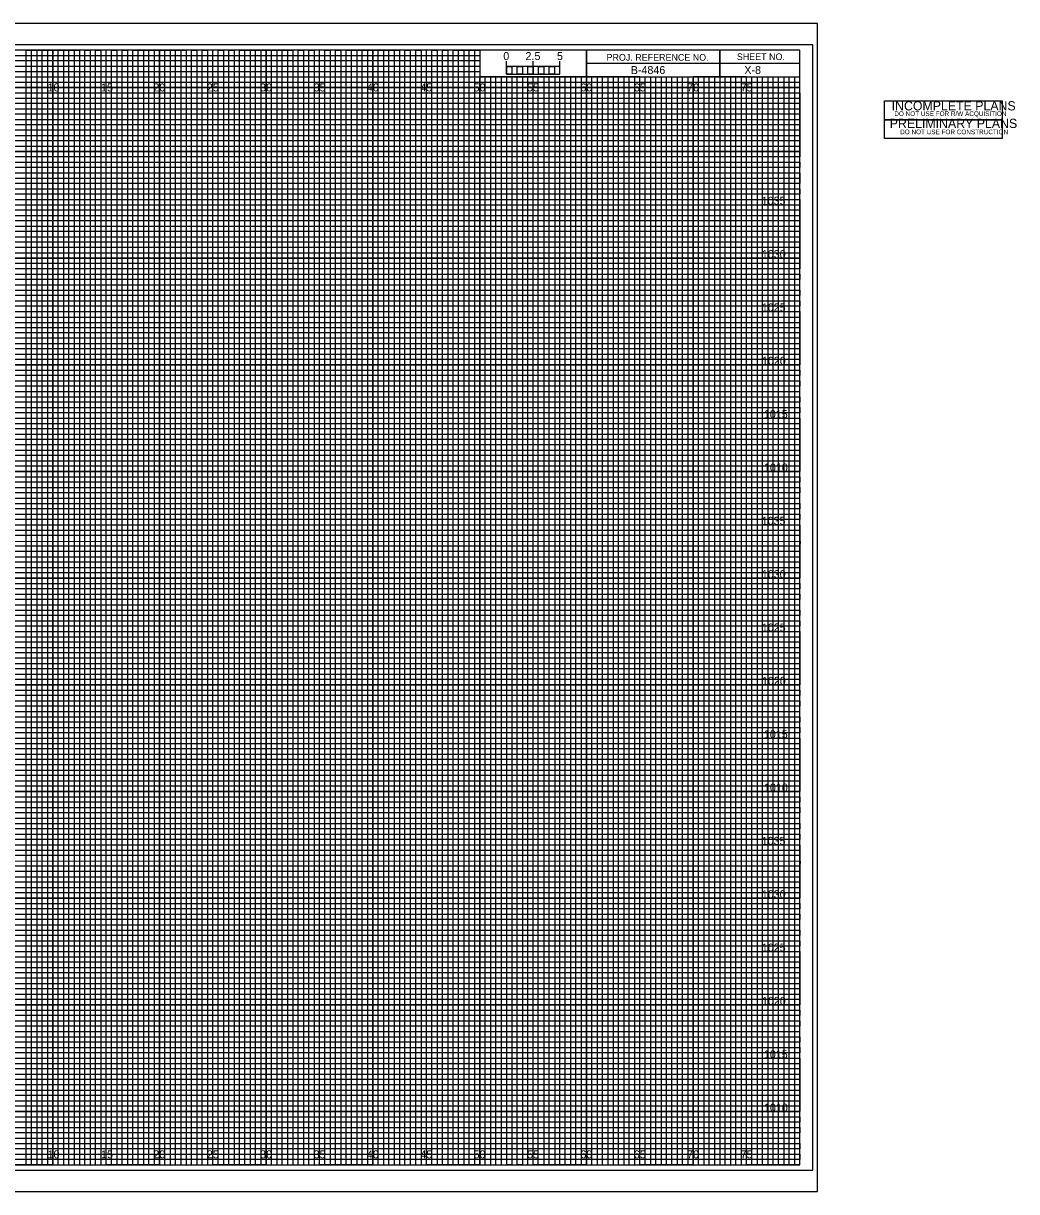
# Model space of a CAD drawing. Extents: x -7 to 180, y -2 to 107.
# Drawn here: x 87.2 to 180.3, y -2.5 to 107 of the extents above; entities that cross this region are included whole.
import ezdxf

# ---------------------------------------------------------------- set-up
doc = ezdxf.new("R2010")
doc.units = 0
for name, color, linetype in [('Default', 7, 'Continuous'), ('Exist Cross Section Cell', 7, 'Continuous'), ('Exist XS Center Line Elevation Label', 7, 'Continuous'), ('Exist XS Ground Line', 7, 'Continuous'), ('Prop CMT Concrete Structures', 7, 'Continuous'), ('Prop CMT Guardrail Graphics', 7, 'Continuous'), ('Prop CMT Guardrail Widen Shoulder', 7, 'Continuous'), ('Prop CMT Pvmt Course 1', 7, 'Continuous'), ('Prop CMT Pvmt Surface', 7, 'Continuous'), ('Prop CMT Pvmt Surface Shoulder', 7, 'Continuous'), ('Prop CMT Shld Paved Course 1', 7, 'Continuous'), ('Prop CMT Shoulder Point', 7, 'Continuous'), ('Prop CMT Slope Grass', 7, 'Continuous'), ('Prop CMT Subgrade Earthwork', 7, 'Continuous'), ('Prop XS SE Text', 7, 'Continuous'), ('Typical Text Label CELL', 7, 'Continuous')]:
    doc.layers.add(name, color=color, linetype=linetype)

msp = doc.modelspace()

# ---------------------------------------------------------------- linework, layer by layer
at = {"layer": 'Default'}
for points in [[(167.92, 97.97), (167.92, 99.73), (178.95, 99.73), (178.95, 97.97)], [(167.92, 96.2), (167.92, 97.97), (178.95, 97.97), (178.95, 96.2)]]:
    msp.add_lwpolyline(points, close=True, dxfattribs=at)
at = {"layer": 'Exist XS Center Line Elevation Label'}
for points in [[(82.5, 0), (87.5, 0), (87.5, 104.5), (92.5, 104.5), (92.5, 0), (97.5, 0), (97.5, 104.5), (102.5, 104.5), (102.5, 0), (107.5, 0), (107.5, 104.5), (112.5, 104.5), (112.5, 0), (117.5, 0), (117.5, 104.5), (122.5, 104.5), (122.5, 0), (127.5, 0), (127.5, 104.5), (129.97, 104.5), (130, 104.5), (130, 102), (132.5, 102), (132.5, 0), (137.5, 0), (137.5, 102), (142.5, 102), (142.5, 0), (147.5, 0), (147.5, 102), (152.5, 102), (152.5, 0), (157.5, 0), (157.5, 102)], [(0, 102), (137.5, 102)], [(0, 92.5), (160, 92.5), (160, 97.5), (0, 97.5)], [(0, 82.5), (160, 82.5), (160, 87.5), (0, 87.5)], [(0, 72.5), (160, 72.5), (160, 77.5), (0, 77.5)], [(0, 62.5), (160, 62.5), (160, 67.5), (0, 67.5)], [(0, 52.5), (160, 52.5), (160, 57.5), (0, 57.5)], [(0, 42.5), (160, 42.5), (160, 47.5), (0, 47.5)], [(0, 32.5), (160, 32.5), (160, 37.5), (0, 37.5)], [(0, 22.5), (160, 22.5), (160, 27.5), (0, 27.5)], [(0, 12.5), (160, 12.5), (160, 17.5), (0, 17.5)], [(0, 2.5), (160, 2.5), (160, 7.5), (0, 7.5)]]:
    msp.add_lwpolyline(points, dxfattribs=at)
at = {"layer": 'Exist XS Ground Line'}
for p, q in [((95, 104.5), (90, 104.5)), ((90, 104.5), (90, 0)), ((95, 0), (95, 104.5)), ((105, 104.5), (100, 104.5)), ((100, 104.5), (100, 0)), ((105, 0), (105, 104.5)), ((115, 104.5), (110, 104.5)), ((110, 104.5), (110, 0)), ((115, 0), (115, 104.5)), ((125, 104.5), (120, 104.5)), ((120, 104.5), (120, 0)), ((125, 0), (125, 104.5)), ((130, 104.5), (130, 0)), ((135, 0), (135, 102)), ((145, 102), (140, 102)), ((140, 102), (140, 0)), ((145, 0), (145, 102)), ((155, 102), (150, 102)), ((150, 102), (150, 0)), ((155, 0), (155, 102)), ((90, 0), (85, 0)), ((100, 0), (95, 0)), ((110, 0), (105, 0)), ((120, 0), (115, 0)), ((130, 0), (125, 0)), ((140, 0), (135, 0)), ((150, 0), (145, 0)), ((160, 0), (155, 0)), ((160, 0), (160, 0))]:
    msp.add_line(p, q, dxfattribs=at)
for points in [[(0, 100), (160, 100), (160, 95), (0, 95)], [(0, 90), (160, 90), (160, 85), (0, 85)], [(0, 80), (160, 80), (160, 75), (0, 75)], [(0, 70), (160, 70), (160, 65), (0, 65)], [(0, 60), (160, 60), (160, 55), (0, 55)], [(0, 50), (160, 50), (160, 45), (0, 45)], [(0, 40), (160, 40), (160, 35), (0, 35)], [(0, 30), (160, 30), (160, 25), (0, 25)], [(0, 20), (160, 20), (160, 15), (0, 15)], [(0, 10), (160, 10), (160, 5), (0, 5)]]:
    msp.add_lwpolyline(points, dxfattribs=at)
at = {"layer": 'Prop CMT Concrete Structures'}
for p, q in [((90, 0), (90, 104.5)), ((95, 0), (95, 104.5)), ((100, 0), (100, 104.5)), ((105, 0), (105, 104.5)), ((110, 0), (110, 104.5)), ((115, 0), (115, 104.5)), ((120, 0), (120, 104.5)), ((125, 0), (125, 104.5)), ((130, 0), (130, 101.84)), ((135, 0), (135, 101.84)), ((140, 0), (140, 101.84)), ((145, 0), (145, 101.84)), ((150, 0), (150, 101.84)), ((155, 0), (155, 101.84)), ((0, 100), (160, 100)), ((0, 95), (160, 95)), ((0, 90), (160, 90)), ((0, 85), (160, 85)), ((0, 80), (160, 80)), ((0, 75), (160, 75)), ((0, 70), (160, 70)), ((0, 65), (160, 65)), ((0, 60), (160, 60)), ((0, 55), (160, 55)), ((0, 50), (160, 50)), ((0, 45), (160, 45)), ((0, 40), (160, 40)), ((0, 35), (160, 35)), ((0, 30), (160, 30)), ((0, 25), (160, 25)), ((0, 20), (160, 20)), ((0, 15), (160, 15)), ((0, 10), (160, 10)), ((0, 5), (160, 5))]:
    msp.add_line(p, q, dxfattribs=at)
at = {"layer": 'Prop CMT Guardrail Widen Shoulder'}
for p, q in [((161.65, 107), (-6.7, 107)), ((-6.7, -2.5), (161.65, -2.5))]:
    msp.add_line(p, q, dxfattribs=at)
at = {"layer": 'Prop CMT Pvmt Course 1'}
msp.add_lwpolyline([(-6.7, -2.5), (161.65, -2.5), (161.65, 107), (-6.7, 107)], close=True, dxfattribs=at)
at = {"layer": 'Prop CMT Pvmt Surface'}
for p, q in [((133.5, 102), (133, 102)), ((133, 102), (133, 0)), ((133.5, 0), (133.5, 102)), ((134.5, 102), (134, 102)), ((134, 102), (134, 0)), ((134.5, 0), (134.5, 102)), ((133, 0), (132.5, 0)), ((134, 0), (133.5, 0))]:
    msp.add_line(p, q, dxfattribs=at)
for points in [[(87.5, 0), (88, 0), (88, 104.5), (88.5, 104.5), (88.5, 0)], [(88.5, 0), (89, 0), (89, 104.5), (89.5, 104.5), (89.5, 0)], [(90, 0), (90.5, 0), (90.5, 104.5), (91, 104.5), (91, 0)], [(91, 0), (91.5, 0), (91.5, 104.5), (92, 104.5), (92, 0)], [(92.5, 0), (93, 0), (93, 104.5), (93.5, 104.5), (93.5, 0)], [(93.5, 0), (94, 0), (94, 104.5), (94.5, 104.5), (94.5, 0)], [(95, 0), (95.5, 0), (95.5, 104.5), (96, 104.5), (96, 0)], [(96, 0), (96.5, 0), (96.5, 104.5), (97, 104.5), (97, 0)], [(97.5, 0), (98, 0), (98, 104.5), (98.5, 104.5), (98.5, 0)], [(98.5, 0), (99, 0), (99, 104.5), (99.5, 104.5), (99.5, 0)], [(100, 0), (100.5, 0), (100.5, 104.5), (101, 104.5), (101, 0)], [(101, 0), (101.5, 0), (101.5, 104.5), (102, 104.5), (102, 0)], [(102.5, 0), (103, 0), (103, 104.5), (103.5, 104.5), (103.5, 0)], [(103.5, 0), (104, 0), (104, 104.5), (104.5, 104.5), (104.5, 0)], [(105, 0), (105.5, 0), (105.5, 104.5), (106, 104.5), (106, 0)], [(106, 0), (106.5, 0), (106.5, 104.5), (107, 104.5), (107, 0)], [(107.5, 0), (108, 0), (108, 104.5), (108.5, 104.5), (108.5, 0)], [(108.5, 0), (109, 0), (109, 104.5), (109.5, 104.5), (109.5, 0)], [(110, 0), (110.5, 0), (110.5, 104.5), (111, 104.5), (111, 0)], [(111, 0), (111.5, 0), (111.5, 104.5), (112, 104.5), (112, 0)], [(112.5, 0), (113, 0), (113, 104.5), (113.5, 104.5), (113.5, 0)], [(113.5, 0), (114, 0), (114, 104.5), (114.5, 104.5), (114.5, 0)], [(115, 0), (115.5, 0), (115.5, 104.5), (116, 104.5), (116, 0)], [(116, 0), (116.5, 0), (116.5, 104.5), (117, 104.5), (117, 0)], [(117.5, 0), (118, 0), (118, 104.5), (118.5, 104.5), (118.5, 0)], [(118.5, 0), (119, 0), (119, 104.5), (119.5, 104.5), (119.5, 0)], [(120, 0), (120.5, 0), (120.5, 104.5), (121, 104.5), (121, 0)], [(121, 0), (121.5, 0), (121.5, 104.5), (122, 104.5), (122, 0)], [(122.5, 0), (123, 0), (123, 104.5), (123.5, 104.5), (123.5, 0)], [(123.5, 0), (124, 0), (124, 104.5), (124.5, 104.5), (124.5, 0)], [(125, 0), (125.5, 0), (125.5, 104.5), (126, 104.5), (126, 0)], [(126, 0), (126.5, 0), (126.5, 104.5), (127, 104.5), (127, 0)], [(127.5, 0), (128, 0), (128, 104.5), (128.5, 104.5), (128.5, 0)], [(128.5, 0), (129, 0), (129, 104.5), (129.5, 104.5), (129.5, 0)], [(130, 0), (130.5, 0), (130.5, 102), (131.01, 102), (131.01, 0)], [(131, 0), (131.5, 0), (131.5, 102), (132, 102), (132, 0)], [(135, 0), (135.49, 0), (135.49, 102), (136, 102), (136, 0)], [(136, 0), (136.5, 0), (136.5, 102), (137.03, 102), (137.03, 0)], [(137.5, 0), (138, 0), (138, 102), (138.5, 102), (138.5, 0)], [(138.5, 0), (139, 0), (139, 102), (139.5, 102), (139.5, 0)], [(140, 0), (140.5, 0), (140.5, 102), (141, 102), (141, 0)], [(141, 0), (141.5, 0), (141.5, 102), (142, 102), (142, 0)], [(142.5, 0), (143, 0), (143, 102), (143.5, 102), (143.5, 0)], [(143.5, 0), (144, 0), (144, 102), (144.5, 102), (144.5, 0)], [(145, 0), (145.5, 0), (145.5, 102), (146, 102), (146, 0)], [(146, 0), (146.5, 0), (146.5, 102), (147, 102), (147, 0)], [(147.5, 0), (148, 0), (148, 102), (148.5, 102), (148.5, 0)], [(148.5, 0), (149, 0), (149, 102), (149.5, 102), (149.5, 0)], [(150, 0), (150.5, 0), (150.5, 102), (151, 102), (151, 0)], [(151, 0), (151.5, 0), (151.5, 102), (152, 102), (152, 0)], [(152.5, 0), (153, 0), (153, 102), (153.5, 102), (153.5, 0)], [(153.5, 0), (154, 0), (154, 102), (154.5, 102), (154.5, 0)], [(155, 0), (155.5, 0), (155.5, 102), (156, 102), (156, 0)], [(156, 0), (156.5, 0), (156.5, 102), (157, 102), (157, 0)], [(157.5, 0), (158, 0), (158, 102), (158.5, 102), (158.5, 0)], [(158.5, 0), (159, 0), (159, 102), (159.5, 102), (159.5, 0)]]:
    msp.add_lwpolyline(points, dxfattribs=at)
at = {"layer": 'Prop CMT Pvmt Surface Shoulder'}
for p, q in [((132.5, 102.25), (132.5, 103.45)), ((132.5, 102.95), (132.5, 103.45)), ((135, 102.25), (135, 103.45)), ((137.5, 102.25), (137.5, 103.45)), ((137.5, 102.95), (137.5, 103.45))]:
    msp.add_line(p, q, dxfattribs=at)
for points in [[(137.5, 102.95), (132.5, 102.95), (132.5, 102.25), (137.5, 102.25)], [(132.5, 102.95), (133, 102.95), (133, 102.25), (132.5, 102.25)], [(133.5, 102.95), (134, 102.95), (134, 102.25), (133.5, 102.25)], [(134.5, 102.95), (135, 102.95), (135, 102.25), (134.5, 102.25)], [(135.5, 102.95), (136, 102.95), (136, 102.25), (135.5, 102.25)], [(136.5, 102.95), (137, 102.95), (137, 102.25), (136.5, 102.25)]]:
    msp.add_lwpolyline(points, close=True, dxfattribs=at)
at = {"layer": 'Prop CMT Shld Paved Course 1'}
for p, q in [((0, 104), (130, 104)), ((130, 103.49), (0, 103.49)), ((0, 103), (130, 103)), ((130, 104), (130, 103.49)), ((130, 103), (130, 102.45)), ((130, 102.45), (0, 102.45)), ((0, 101.5), (160, 101.5))]:
    msp.add_line(p, q, dxfattribs=at)
for points in [[(0, 101), (135, 101), (160, 101), (160, 101), (0, 101)], [(0, 100.5), (160, 100.5), (160, 99.5), (0, 99.5)], [(0, 99), (160, 99), (160, 98.5), (0, 98.49)], [(0, 98), (160, 98), (160, 97), (0, 97)], [(0, 96.5), (160, 96.5), (160, 96), (0, 96)], [(0, 95.5), (160, 95.5), (160, 94.5), (0, 94.5)], [(0, 94), (160, 94), (160, 93.5), (0, 93.5)], [(0, 93), (160, 93), (160, 92), (0, 92)], [(0, 91.5), (160, 91.5), (160, 91), (0, 91)], [(0, 90.5), (160, 90.5), (160, 89.5), (0, 89.5)], [(0, 89), (160, 89), (160, 88.5), (0, 88.5)], [(0, 88), (160, 88), (160, 86.98), (160, 86.5), (160, 86), (0, 86)], [(0, 87), (160, 87), (160, 86.5), (0, 86.5)], [(0, 85.5), (160, 85.5), (160, 84.5), (0, 84.52)], [(0, 84.52), (160, 84.5), (160, 84), (0, 84)], [(0, 83.5), (160, 83.5), (160, 83), (0, 83)], [(0, 82), (160, 82), (160, 81.5), (0, 81.5)], [(0, 81), (160, 81), (160, 80.5), (0, 80.5)], [(-0.04, 79.45), (160, 79.45), (160, 78.94), (-0.04, 78.94)], [(0, 78.5), (160, 78.5), (160, 78), (0, 78)], [(0, 77), (160, 77), (160, 76.5), (0, 76.5)], [(0, 76), (160, 76), (160, 75.5), (0, 75.5)], [(0, 74.5), (160, 74.5), (160, 74), (0, 74)], [(0, 73.5), (160, 73.5), (160, 73), (0, 73)], [(0, 72), (160, 72), (160, 71.5), (0, 71.5)], [(0, 71), (160, 71), (160, 70.5), (0, 70.5)], [(0, 69.5), (160, 69.5), (160, 68.99), (0, 69)], [(0, 68.5), (160, 68.5), (160, 68), (0, 68)], [(0, 67), (160, 67), (160, 66.5), (0, 66.5)], [(0, 66), (160, 66), (160, 65.5), (0, 65.5)], [(0, 64.5), (160, 64.5), (160, 64), (0, 64)], [(0, 63.5), (160, 63.5), (160, 63), (0, 63)], [(0, 62), (160, 62), (160, 61.5), (0, 61.5)], [(0, 61), (160, 61), (160, 60.5), (0, 60.5)], [(0, 59.5), (160, 59.5), (160, 59), (0, 59)], [(0, 58.5), (160.03, 58.45), (160, 58), (0, 58)], [(0, 57), (160, 57), (160, 56.5), (0, 56.5)], [(0, 56), (160, 56), (160, 55.5), (0, 55.5)], [(0, 54.5), (160, 54.5), (160, 54), (0, 54)], [(0, 53.5), (160, 53.5), (160, 53), (0, 53)], [(0, 52), (160, 52), (160, 51.5), (0, 51.5)], [(0, 51), (160, 51), (160, 50.5), (0, 50.5)], [(0, 49.5), (160, 49.5), (160, 49), (0, 49)], [(0, 48.5), (160, 48.5), (160, 48), (0, 48)], [(0, 47), (160, 47), (160, 46.5), (0, 46.5)], [(0, 46), (160, 46), (160, 45.5), (0, 45.5)], [(0, 44.5), (160, 44.5), (160, 44), (0, 44)], [(0, 43.5), (160, 43.5), (160, 43), (0, 43)], [(0, 42), (160, 42), (160, 41.5), (0, 41.5)], [(0, 41), (160, 41), (160, 40.5), (0, 40.5)], [(0, 39.5), (160, 39.5), (160, 38.99), (0, 39)], [(0, 38.5), (160, 38.5), (160, 38), (0, 38)], [(0, 37), (160, 37), (160, 36.5), (0, 36.5)], [(0, 36), (160, 36), (160, 35.5), (0, 35.5)], [(0, 34.5), (160, 34.5), (160, 34), (0, 34)], [(0, 33.5), (160, 33.5), (160, 33), (0, 33)], [(0, 32), (160, 32), (160, 31.5), (0, 31.5)], [(0, 31), (160, 31), (160, 30.5), (0, 30.5)], [(0, 29.5), (160, 29.5), (160, 29), (0, 29)], [(0, 28.5), (160.03, 28.46), (160, 28), (0, 28)], [(0, 27), (160, 27), (160, 26.5), (0, 26.5)], [(0, 26), (160, 26), (160, 25.5), (0, 25.5)], [(0, 24.5), (160, 24.5), (160, 24), (0, 24)], [(0, 23.5), (160, 23.5), (160, 23), (0, 23)], [(0, 22), (160, 22), (160, 21.5), (0, 21.5)], [(0, 21), (160, 21), (160, 20.5), (0, 20.5)], [(0, 19.5), (160, 19.5), (160, 19), (0, 19)], [(0, 18.5), (160, 18.5), (160, 18), (0, 18)], [(0, 17), (160, 17), (160, 16.5), (0, 16.5)], [(0, 16), (160, 16), (160, 15.5), (0, 15.5)], [(0, 14.5), (160, 14.5), (160, 14), (0, 14)], [(0, 13.5), (160, 13.5), (160, 13), (0, 13)], [(0, 12), (160, 12), (160, 11.5), (0, 11.5)], [(0, 11), (160, 11), (160, 10.5), (0, 10.5)], [(0, 9.5), (160, 9.5), (160, 9), (0, 9)], [(0, 8.5), (160, 8.5), (160, 8), (0, 8)], [(0, 7), (160, 7), (160, 6.5), (0, 6.5)], [(0, 6), (160, 6), (160, 5.5), (0, 5.5)], [(0, 4.5), (160, 4.5), (160, 4), (0, 4)], [(0, 3.5), (160, 3.5), (160, 3), (0, 3)], [(0, 2), (160, 2), (160, 1.5), (0, 1.5)], [(0, 1), (160, 1), (160, 0.5), (0, 0.5)]]:
    msp.add_lwpolyline(points, dxfattribs=at)
at = {"layer": 'Prop CMT Slope Grass'}
msp.add_lwpolyline([(-5.4, -0.5), (161.2, -0.5), (161.2, 105), (-5.4, 105)], close=True, dxfattribs=at)
at = {"layer": 'Prop CMT Subgrade Earthwork'}
for p, q in [((152.5, 104.5), (152.5, 102)), ((152.5, 102), (152.5, 104.5)), ((160, 103.25), (140, 103.25)), ((140, 103.25), (140, 102)), ((140, 102), (160, 102))]:
    msp.add_line(p, q, dxfattribs=at)
for points in [[(160, 104.5), (0, 104.5), (0, 0), (160, 0)], [(140, 104.5), (130, 104.5), (130, 102.02), (140, 102.02)], [(160, 104.5), (140, 104.5), (140, 102), (160, 102)]]:
    msp.add_lwpolyline(points, close=True, dxfattribs=at)

# ---------------------------------------------------------------- texts
at = {"layer": 'Default'}
for s, height, p in [('INCOMPLETE PLANS', 0.864, (168.59, 98.84)), ('DO NOT USE FOR R/W ACQUISITION', 0.432, (168.84, 98.32)), ('PRELIMINARY PLANS', 0.864, (168.41, 97.19)), ('DO NOT USE FOR CONSTRUCTION', 0.432, (169.39, 96.61))]:
    msp.add_text(s, height=height, dxfattribs=at).set_placement(p)
at = {"layer": 'Exist Cross Section Cell'}
for s, p in [('10', (89.52, 100.62)), ('15', (94.53, 100.62)), ('20', (99.43, 100.62)), ('25', (104.44, 100.62)), ('30', (109.43, 100.62)), ('35', (114.44, 100.62)), ('40', (119.43, 100.62)), ('45', (124.44, 100.62)), ('50', (129.43, 100.62)), ('55', (134.44, 100.62)), ('60', (139.43, 100.62)), ('65', (144.44, 100.62)), ('70', (149.43, 100.62)), ('75', (154.44, 100.62)), ('10', (89.52, 0.62)), ('15', (94.53, 0.62)), ('20', (99.43, 0.62)), ('25', (104.44, 0.62)), ('30', (109.43, 0.62)), ('35', (114.44, 0.62)), ('40', (119.43, 0.62)), ('45', (124.44, 0.62)), ('50', (129.43, 0.62)), ('55', (134.44, 0.62)), ('60', (139.43, 0.62)), ('65', (144.44, 0.62)), ('70', (149.43, 0.62)), ('75', (154.44, 0.62))]:
    msp.add_text(s, height=0.75, dxfattribs=at).set_placement(p)
at = {"layer": 'Prop CMT Guardrail Graphics'}
msp.add_text('B-4846', height=0.75, dxfattribs=at).set_placement((144.15, 102.25))
at = {"layer": 'Prop CMT Pvmt Surface Shoulder'}
msp.add_text('0', height=0.75, dxfattribs=at).set_placement((132.21, 103.56))
at = {"layer": 'Prop CMT Shoulder Point'}
for s, p in [('2.5', (134.29, 103.56)), ('5', (137.24, 103.56))]:
    msp.add_text(s, height=0.75, dxfattribs=at).set_placement(p)
at = {"layer": 'Prop CMT Subgrade Earthwork'}
for s, p in [('PROJ. REFERENCE NO.', (141.88, 103.5)), ('SHEET NO.', (154.09, 103.56))]:
    msp.add_text(s, height=0.625, dxfattribs=at).set_placement(p)
at = {"layer": 'Prop XS SE Text'}
msp.add_text('X-8', height=0.75, dxfattribs=at).set_placement((154.79, 102.25))
at = {"layer": 'Typical Text Label CELL'}
for s, p in [('1035', (156.42, 90)), ('1030', (156.43, 85)), ('1025', (156.43, 80)), ('1020', (156.44, 75)), ('1015', (156.62, 70)), ('1010', (156.63, 65)), ('1035', (156.42, 60)), ('1030', (156.43, 55)), ('1025', (156.43, 50)), ('1020', (156.44, 45)), ('1015', (156.62, 40)), ('1010', (156.63, 35)), ('1035', (156.42, 30)), ('1030', (156.43, 25)), ('1025', (156.43, 20)), ('1020', (156.44, 15)), ('1015', (156.62, 10)), ('1010', (156.63, 5))]:
    msp.add_text(s, height=0.75, dxfattribs=at).set_placement(p)

doc.saveas('drawing.dxf')
